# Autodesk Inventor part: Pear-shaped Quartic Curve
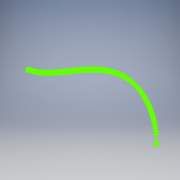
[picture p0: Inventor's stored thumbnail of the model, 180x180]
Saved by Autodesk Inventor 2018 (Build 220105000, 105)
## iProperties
Created: 2008-02
Part Number: Pear-shaped Quartic Curve
Document SubType Name: Modeling
Designer: Autodesk, Inc.
Density: 1 g/cm^3
Material: Generic
Appearance: Default
Author: Autodesk, Inc.
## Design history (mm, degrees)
sketch "Sketch1"
  geometry: 301 further points
  constraints: 301 other
